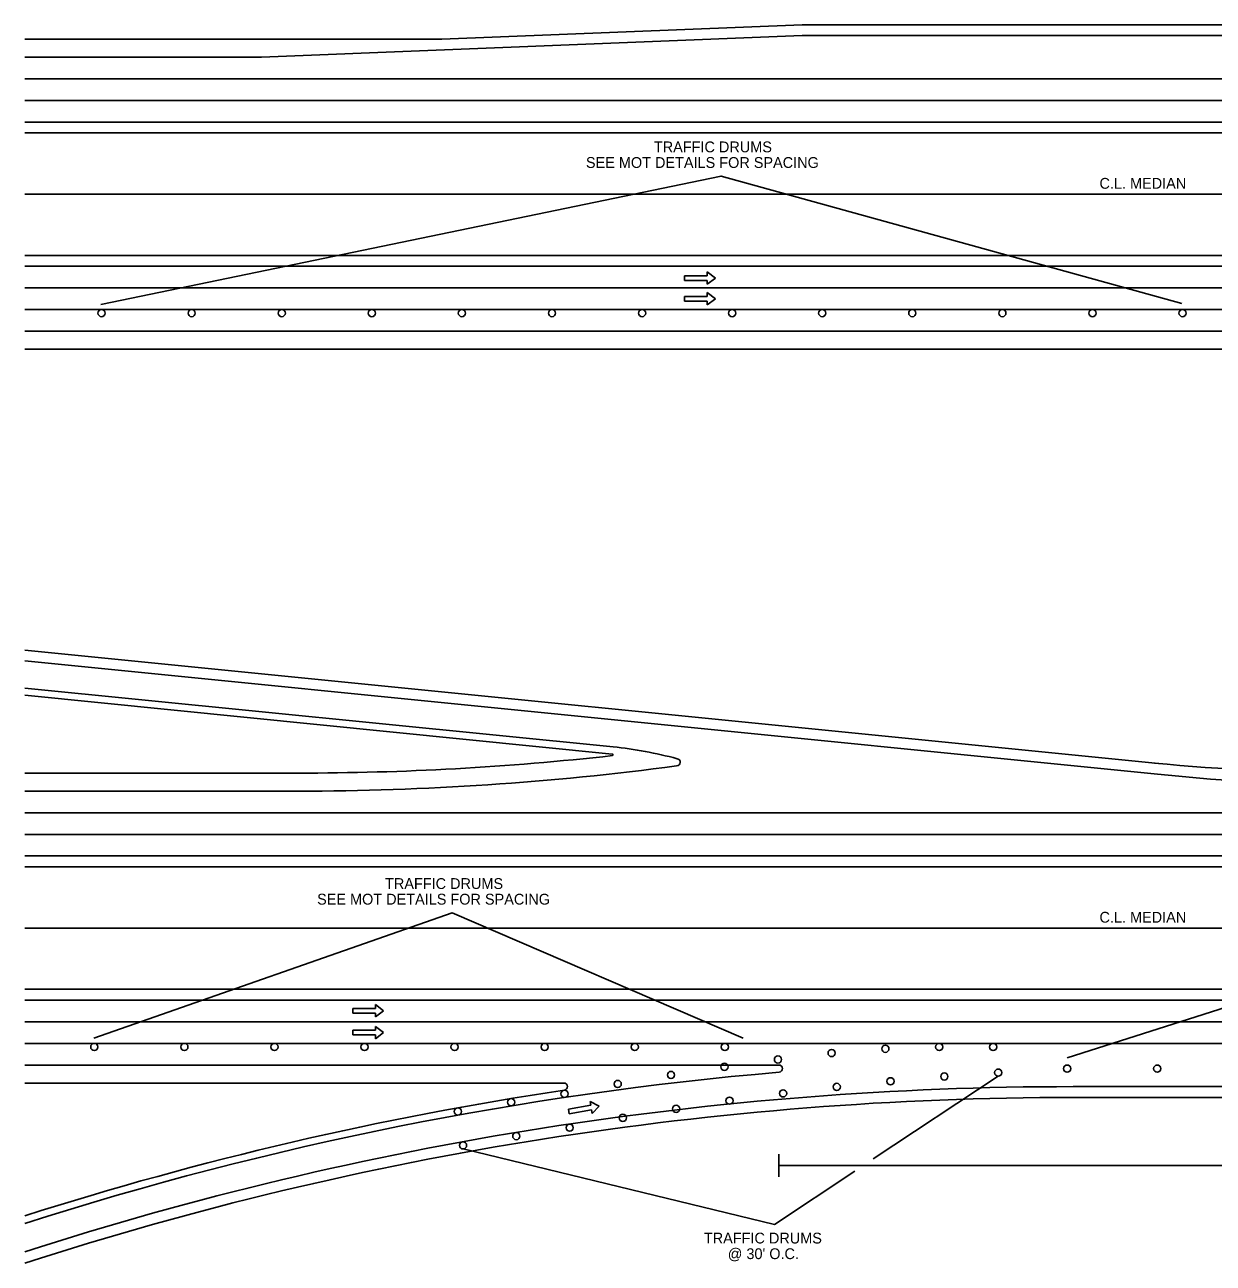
# Model space of a CAD drawing. Extents: x 1373848 to 1374003, y 380642 to 381248.
# Drawn here: x 1373848.2 to 1373914.2, y 380815.2 to 380883.9 of the extents above; entities that cross this region are included whole.
import ezdxf

# ---------------------------------------------------------------- set-up
doc = ezdxf.new("R2010")
doc.units = 0
for name, color, linetype in [('Default', 7, 'Continuous'), ('R_Horz Alg', 7, 'Continuous'), ('R_MOT', 7, 'Continuous')]:
    doc.layers.add(name, color=color, linetype=linetype)

# ---------------------------------------------------------------- blocks, each defined once
blk = doc.blocks.new('SARROW')
at = {"layer": 'Default'}
for p, q in [((15.6, 3.2), (-13.8, 3.2)), ((-13.8, 3.2), (-13.8, -2.8)), ((15.6, 8.2), (15.6, 3.2)), ((15.6, 8.2), (26, 0.2)), ((26, 0.2), (15.6, -7.8)), ((15.6, -2.8), (-13.8, -2.8)), ((15.6, -2.8), (15.6, -7.8))]:
    blk.add_line(p, q, dxfattribs=at)

msp = doc.modelspace()

# ---------------------------------------------------------------- linework, layer by layer
at = {"layer": 'Default'}
for p, q in [((1373891.355, 380883.909), (1373871.355, 380883.109)), ((1373945.02, 380883.909), (1373891.355, 380883.909)), ((1373871.355, 380883.109), (1373848.214, 380883.109)), ((1373891.355, 380883.309), (1373861.355, 380882.109)), ((1373945.02, 380883.309), (1373891.355, 380883.309)), ((1373861.355, 380882.109), (1373848.214, 380882.109)), ((1373848.214, 380880.909), (1374003.214, 380880.909)), ((1373848.214, 380879.709), (1374003.214, 380879.709)), ((1373848.214, 380878.509), (1374003.214, 380878.509)), ((1373848.214, 380877.909), (1374003.214, 380877.909)), ((1373848.214, 380874.509), (1374003.214, 380874.509)), ((1373848.214, 380871.109), (1374003.214, 380871.109)), ((1373848.214, 380870.509), (1374003.214, 380870.509)), ((1373848.214, 380869.309), (1374003.214, 380869.309)), ((1373848.214, 380868.109), (1374003.214, 380868.109)), ((1373848.214, 380866.909), (1373921.443, 380866.909)), ((1373848.214, 380865.909), (1373929.25, 380865.909)), ((1373848.214, 380849.21), (1373911.145, 380842.92)), ((1373848.214, 380848.607), (1373911.086, 380842.323)), ((1373848.214, 380847.1), (1373880.865, 380843.836)), ((1373848.214, 380846.698), (1373880.825, 380843.438)), ((1373848.214, 380842.381), (1373863.397, 380842.381)), ((1373863.397, 380841.381), (1373848.214, 380841.381)), ((1374003.214, 380840.181), (1373848.214, 380840.181)), ((1374003.214, 380838.981), (1373848.214, 380838.981)), ((1374003.214, 380837.781), (1373848.214, 380837.781)), ((1374003.214, 380837.181), (1373848.214, 380837.181)), ((1374003.214, 380833.781), (1373848.214, 380833.781)), ((1374003.214, 380830.381), (1373848.214, 380830.381)), ((1374003.214, 380829.781), (1373848.214, 380829.781)), ((1374003.214, 380828.581), (1373848.214, 380828.581)), ((1374003.214, 380827.381), (1373848.214, 380827.381)), ((1373890.072, 380826.181), (1373848.214, 380826.181)), ((1373878.136, 380825.181), (1373848.214, 380825.181)), ((1373906.407, 380824.981), (1373960.072, 380824.981)), ((1373906.407, 380824.381), (1373960.072, 380824.381)), ((1373890.072, 380821.233), (1373890.072, 380819.983)), ((1373960.072, 380820.608), (1373890.072, 380820.608))]:
    msp.add_line(p, q, dxfattribs=at)
for centre, radius, start, end in [((1373878.701, 380822.194), 21.75, 74.76438, 84.29167), ((1373863.397, 380999.581), 157.2, 270, 276.36869), ((1373880.824, 380843.394), 0.0444, 284.39417, 88.34322), ((1373884.397, 380842.981), 0.2, 270, 84.29167), ((1373922.177, 380955.458), 113.078, 264.29167, 270), ((1373863.397, 380999.581), 158.2, 270, 277.62815), ((1373929.984, 381031.381), 190, 264.29167, 270), ((1373906.407, 380635.731), 190.75, 94.90749, 107.76292), ((1373890.072, 380825.981), 0.2, 274.90749, 90), ((1373906.407, 380635.731), 189.25, 90, 107.90846), ((1373878.136, 380824.981), 0.2, 278.49632, 90), ((1373906.407, 380635.731), 191.15, 98.49632, 107.72452), ((1373906.407, 380635.731), 188.65, 90, 107.96736)]:
    msp.add_arc(centre, radius, start, end, dxfattribs=at)
at = {"layer": 'R_Horz Alg'}
for centre in [(1373852.478, 380867.909), (1373857.478, 380867.909), (1373862.478, 380867.909), (1373867.478, 380867.909), (1373872.478, 380867.909), (1373877.478, 380867.909), (1373882.478, 380867.909), (1373887.478, 380867.909), (1373892.478, 380867.909), (1373897.478, 380867.909), (1373902.478, 380867.909), (1373907.478, 380867.909), (1373912.478, 380867.909), (1373852.072, 380827.181), (1373857.072, 380827.181), (1373862.072, 380827.181), (1373867.072, 380827.181), (1373872.072, 380827.181), (1373877.072, 380827.181), (1373882.072, 380827.181), (1373887.072, 380827.181), (1373893, 380826.845), (1373895.983, 380827.082), (1373898.972, 380827.181), (1373901.964, 380827.181), (1373890.021, 380826.487), (1373884.083, 380825.628), (1373887.049, 380826.081), (1373899.255, 380825.542), (1373902.247, 380825.759), (1373906.072, 380825.981), (1373911.072, 380825.981), (1373881.125, 380825.129), (1373893.283, 380824.966), (1373896.267, 380825.278), (1373875.212, 380824.116), (1373878.175, 380824.583), (1373887.332, 380824.202), (1373890.305, 380824.607), (1373872.256, 380823.602), (1373884.367, 380823.749), (1373878.459, 380822.703), (1373881.409, 380823.25), (1373875.496, 380822.236), (1373872.54, 380821.722)]:
    msp.add_circle(centre, 0.2, dxfattribs=at)
at = {"layer": 'R_MOT'}
for points in [[(1373852.441, 380868.383), (1373886.868, 380875.508), (1373912.443, 380868.438)], [(1373852.054, 380827.665), (1373871.946, 380834.626), (1373888.095, 380827.665)], [(1373906.081, 380826.579), (1373931.333, 380834.626), (1373955.564, 380826.402)], [(1373895.313, 380820.969), (1373902.247, 380825.559)], [(1373872.54, 380821.522), (1373889.821, 380817.333), (1373894.283, 380820.287)]]:
    msp.add_lwpolyline(points, dxfattribs=at)

# ---------------------------------------------------------------- block references
at = {"layer": 'R_MOT', "xscale": 0.0428571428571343}
for p, yscale, rotation in [((1373885.431, 380869.845), 0.0428571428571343, -8.252131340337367e-12), ((1373885.431, 380868.699), 0.0428571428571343, -8.252131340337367e-12), ((1373867.011, 380829.184), 0.0428571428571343, -8.252131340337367e-12), ((1373867.011, 380827.971), 0.0428571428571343, -8.252131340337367e-12), ((1373878.999, 380823.699), 0.042857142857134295, 9.913114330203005)]:
    msp.add_blockref('SARROW', p, dxfattribs=dict(at, yscale=yscale, rotation=rotation))

# ---------------------------------------------------------------- texts
at = {"layer": 'R_MOT'}
for s, p in [('TRAFFIC DRUMS', (1373883.134, 380876.832)), ('SEE MOT DETAILS FOR SPACING', (1373879.361, 380875.965)), ('C.L. MEDIAN', (1373907.868, 380874.809)), ('TRAFFIC DRUMS', (1373868.212, 380835.95)), ('SEE MOT DETAILS FOR SPACING', (1373864.439, 380835.083)), ('C.L. MEDIAN', (1373907.868, 380834.081)), ('TRAFFIC DRUMS ', (1373885.908, 380816.276)), ("@ 30' O.C.", (1373887.233, 380815.409))]:
    msp.add_text(s, height=0.6, dxfattribs=at).set_placement(p)

doc.saveas('drawing.dxf')
